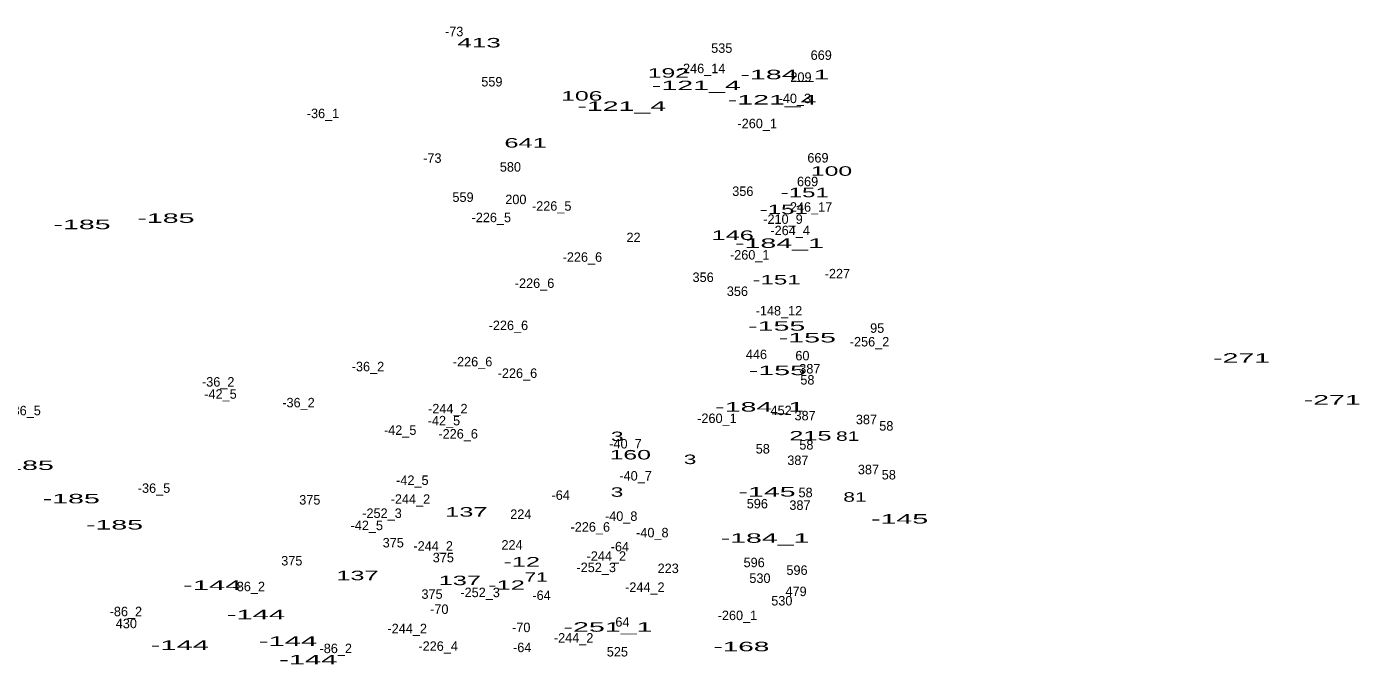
# Model space of a CAD drawing. Extents: x -658595 to -655205, y -1004347 to -1000147.
# Drawn here: x -656989 to -656427, y -1001472 to -1001203 of the extents above; entities that cross this region are included whole.
import ezdxf
from ezdxf.enums import TextEntityAlignment as Align

# ---------------------------------------------------------------- set-up
doc = ezdxf.new("R2010")
doc.units = 0
doc.header["$LTSCALE"] = 1.6
doc.layers.add('24', color=7, linetype='Continuous')

msp = doc.modelspace()

# ---------------------------------------------------------------- texts
at = {"layer": '24'}
for s, p in [('-73', (-656808.311, -1001206.84)), ('535', (-656695.457, -1001213.83)), ('669', (-656653.503, -1001216.79)), ('-246_14', (-656703.749, -1001222.41)), ('559', (-656792.413, -1001228.01)), ('209', (-656662.047, -1001226.07)), ('-40_3', (-656664.631, -1001235.05)), ('-36_1', (-656863.632, -1001241.38)), ('-260_1', (-656680.496, -1001245.63)), ('-73', (-656817.521, -1001260.23)), ('669', (-656654.883, -1001260.1)), ('580', (-656784.591, -1001263.96)), ('669', (-656659.253, -1001270.09)), ('559', (-656804.583, -1001276.72)), ('200', (-656782.295, -1001277.66)), ('356', (-656686.563, -1001274.21)), ('-226_5', (-656767.178, -1001280.44)), ('-246_17', (-656658.671, -1001280.86)), ('-226_5', (-656792.658, -1001285.28)), ('-210_9', (-656669.626, -1001285.98)), ('22', (-656732.667, -1001293.7)), ('-264_4', (-656666.606, -1001290.75)), ('-260_1', (-656683.666, -1001301.05)), ('-226_6', (-656754.243, -1001301.98)), ('356', (-656703.303, -1001310.5)), ('-227', (-656646.691, -1001308.98)), ('-226_6', (-656774.413, -1001313.01)), ('356', (-656688.853, -1001316.41)), ('-148_12', (-656671.343, -1001324.62)), ('-226_6', (-656785.443, -1001330.8)), ('95', (-656629.903, -1001331.95)), ('-256_2', (-656633.128, -1001337.7)), ('-226_6', (-656800.553, -1001346.11)), ('446', (-656680.831, -1001343.05)), ('60', (-656661.427, -1001343.58)), ('-36_2', (-656844.678, -1001348.18)), ('-226_6', (-656781.633, -1001350.97)), ('387', (-656658.303, -1001349.1)), ('-36_2', (-656907.828, -1001354.64)), ('58', (-656659.337, -1001353.79)), ('-42_5', (-656906.877, -1001359.76)), ('-36_5', (-656989.488, -1001366.74)), ('-36_2', (-656873.968, -1001363.4)), ('-244_2', (-656810.991, -1001365.94)), ('452', (-656670.421, -1001366.68)), ('-42_5', (-656812.627, -1001371)), ('-260_1', (-656697.486, -1001370.01)), ('387', (-656660.303, -1001368.88)), ('387', (-656634.433, -1001370.5)), ('58', (-656626.047, -1001373.21)), ('-42_5', (-656831.087, -1001375)), ('-226_6', (-656806.633, -1001376.55)), ('-40_7', (-656736.066, -1001380.75)), ('58', (-656678.157, -1001382.88)), ('58', (-656659.767, -1001381.21)), ('387', (-656663.343, -1001387.72)), ('-42_5', (-656825.947, -1001396.14)), ('-40_7', (-656731.796, -1001394.28)), ('387', (-656633.583, -1001391.62)), ('58', (-656624.997, -1001393.82)), ('-36_5', (-656934.908, -1001399.46)), ('58', (-656660.097, -1001401.33)), ('375', (-656869.193, -1001404.42)), ('-244_2', (-656826.771, -1001404.08)), ('-64', (-656763.385, -1001402.43)), ('596', (-656680.458, -1001406.02)), ('387', (-656662.483, -1001406.65)), ('-252_3', (-656838.752, -1001410.05)), ('224', (-656780.201, -1001410.47)), ('-40_8', (-656737.871, -1001411.29)), ('-42_5', (-656845.177, -1001415.2)), ('-226_6', (-656750.913, -1001415.84)), ('-40_8', (-656724.731, -1001418.24)), ('375', (-656834.003, -1001422.49)), ('-244_2', (-656817.161, -1001423.87)), ('224', (-656783.911, -1001423.42)), ('-64', (-656738.405, -1001424.15)), ('375', (-656876.793, -1001430.1)), ('375', (-656812.893, -1001428.77)), ('-244_2', (-656744.141, -1001428.12)), ('-252_3', (-656748.412, -1001432.9)), ('223', (-656718.037, -1001433.31)), ('596', (-656681.788, -1001430.84)), ('596', (-656663.718, -1001434.08)), ('-86_2', (-656894.938, -1001440.96)), ('-244_2', (-656727.891, -1001441.26)), ('530', (-656679.351, -1001437.47)), ('375', (-656817.653, -1001444.18)), ('-252_3', (-656797.372, -1001443.47)), ('-64', (-656771.455, -1001444.69)), ('530', (-656670.121, -1001446.98)), ('479', (-656664.113, -1001443.03)), ('-86_2', (-656946.778, -1001451.52)), ('-70', (-656814.584, -1001450.55)), ('430', (-656946.585, -1001456.57)), ('-70', (-656780.024, -1001458.23)), ('-64', (-656738.235, -1001455.92)), ('-260_1', (-656688.846, -1001453.16)), ('-244_2', (-656828.111, -1001458.7)), ('-244_2', (-656757.931, -1001462.63)), ('-86_2', (-656858.258, -1001467.09)), ('-226_4', (-656815.072, -1001466.11)), ('-64', (-656779.615, -1001466.67)), ('525', (-656739.477, -1001468.5))]:
    msp.add_text(s, height=4, dxfattribs=at).set_placement(p, align=Align.CENTER)
for s, width, p in [('413', 2.05, (-656797.793, -1001211.55)), ('192', 1.95, (-656717.993, -1001224.32)), ('-184_1', 2.25, (-656668.823, -1001224.98)), ('-121_4', 2.25, (-656706.183, -1001229.57)), ('106', 1.95, (-656754.479, -1001233.99)), ('-121_4', 2.25, (-656737.623, -1001238.31)), ('-121_4', 2.25, (-656674.183, -1001235.63)), ('641', 2, (-656778.188, -1001253.81)), ('100', 1.95, (-656649.15, -1001265.69)), ('-151', 1.9, (-656660.447, -1001274.74)), ('-151', 1.9, (-656669.297, -1001281.87)), ('-185', 2.25, (-656965.261, -1001288.23)), ('-185', 2.25, (-656929.881, -1001285.56)), ('146', 2, (-656690.858, -1001292.76)), ('-184_1', 2.25, (-656671.113, -1001296.13)), ('-151', 1.9, (-656672.337, -1001311.55)), ('-155', 2.25, (-656672.271, -1001331.06)), ('-155', 2.25, (-656659.341, -1001336.01)), ('-271', 2.25, (-656476.205, -1001344.57)), ('-155', 2.25, (-656671.991, -1001349.8)), ('-271', 2.25, (-656437.995, -1001362.24)), ('-184_1', 2.25, (-656679.483, -1001365.19)), ('3', 1.8, (-656739.531, -1001377.63)), ('215', 2, (-656658.057, -1001377.37)), ('81', 1.65, (-656642.327, -1001377.52)), ('160', 1.95, (-656734.039, -1001385.37)), ('-185', 2.25, (-656989.221, -1001389.82)), ('3', 1.8, (-656708.821, -1001387.33)), ('3', 1.8, (-656739.631, -1001401.12)), ('-145', 2.25, (-656676.356, -1001401.03)), ('-185', 2.25, (-656969.821, -1001403.9)), ('81', 1.65, (-656639.287, -1001403.21)), ('137', 2, (-656803.173, -1001409.5)), ('-145', 2.25, (-656620.436, -1001412.45)), ('-185', 2.25, (-656951.571, -1001414.93)), ('-184_1', 2.25, (-656677.203, -1001420.54)), ('-12', 2, (-656779.811, -1001430.55)), ('-144', 2.3, (-656910.352, -1001440.43)), ('137', 2, (-656849.103, -1001436.32)), ('137', 2, (-656805.933, -1001438.41)), ('-12', 2, (-656786.241, -1001440.37)), ('71', 1.65, (-656773.753, -1001437)), ('-144', 2.3, (-656891.912, -1001452.8)), ('-251_1', 2.25, (-656743.447, -1001458.05)), ('-144', 2.3, (-656878.402, -1001464.02)), ('-144', 2.3, (-656924.052, -1001465.73)), ('-168', 2.2, (-656687.175, -1001466.3)), ('-144', 2.3, (-656869.842, -1001471.82))]:
    msp.add_text(s, height=4, dxfattribs=dict(at, width=width)).set_placement(p, align=Align.CENTER)

doc.saveas('drawing.dxf')
